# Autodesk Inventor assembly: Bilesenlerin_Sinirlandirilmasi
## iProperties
Company: Autodesk, Inc.
Shininess: 64.0
Length Units: 11269
Angle Units: 11279
Time Units: 11290
Mass Units: 11283
Length Display Precision: 3
Angle Display Precision: 2
Compacted: True
Created: 2003-12
Part Number: Bilesenlerin_Sinirlandirilmasi
Document SubType Name: Assembly
Catalog Web Link: www.autodesk.com
Vendor: Autodesk, Inc.
Designer: Administrator
Manufacturer: Standard
Standards Organization: Custom
Density: 0.0
Volumn: 0.0
Area: 0.0
PropertySet Name: Model Information
Control State: 0
Master: False
Checked Out: False
Author: Administrator
